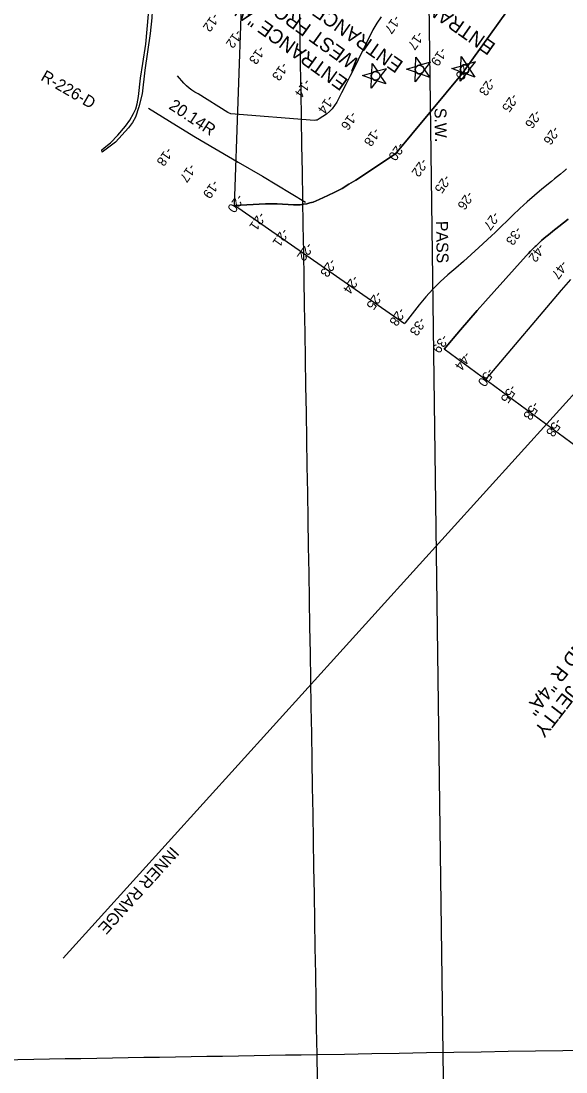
# Model space of a CAD drawing. Extents: x 3879599 to 3900814, y 146526 to 168888.
# Drawn here: x 3887801 to 3889730, y 150452 to 154174 of the extents above; entities that cross this region are included whole.
import ezdxf

# ---------------------------------------------------------------- set-up
doc = ezdxf.new("R2010")
doc.units = 0
for name, color, linetype in [('V-CHAN-NAID', 7, 'Continuous'), ('V-GRID-MAJR', 7, 'Continuous'), ('V-LEVE-TOET', 7, 'Continuous'), ('V-RIVR-JETY', 7, 'Continuous'), ('V-RIVR-RANG', 7, 'Continuous'), ('V-RIVR-RANG-IDEN', 7, 'Continuous'), ('V-STRM-FMON', 7, 'Continuous'), ('V-TOPO-DPTH', 7, 'Continuous'), ('V-TOPO-MAJR', 7, 'Continuous'), ('V-TOPO-MINR', 7, 'Continuous')]:
    doc.layers.add(name, color=color, linetype=linetype)

msp = doc.modelspace()

# ---------------------------------------------------------------- linework, layer by layer
at = {"layer": 'V-CHAN-NAID'}
for points in [[(3889197.6, 154008.2), (3889199, 154046.4), (3889217.6, 154018.6), (3889213, 154017.3), (3889212.4, 154017.3), (3889211.3, 154017.4), (3889210.3, 154017.3), (3889209.3, 154017.2), (3889208.4, 154017), (3889207.5, 154016.8), (3889206.7, 154016.6), (3889205.7, 154016.2), (3889204.9, 154015.8), (3889204, 154015.4), (3889203.3, 154015), (3889202.6, 154014.5), (3889201.7, 154013.8), (3889201.1, 154013.3), (3889200.4, 154012.5), (3889199.9, 154012), (3889199.3, 154011.2), (3889198.8, 154010.5), (3889198.4, 154009.8), (3889197.9, 154009)], [(3889357.3, 154009.9), (3889358.7, 154048.1), (3889377.3, 154020.3), (3889372.7, 154019), (3889372.1, 154019.1), (3889371, 154019.1), (3889370.1, 154019), (3889369, 154018.9), (3889368.1, 154018.7), (3889367.2, 154018.5), (3889366.4, 154018.3), (3889365.4, 154017.9), (3889364.6, 154017.5), (3889363.7, 154017.1), (3889363, 154016.7), (3889362.3, 154016.2), (3889361.4, 154015.5), (3889360.8, 154015), (3889360.1, 154014.2), (3889359.6, 154013.7), (3889359, 154012.9), (3889358.5, 154012.2), (3889358.1, 154011.5), (3889357.6, 154010.7)], [(3889042.1, 153985.6), (3889043.6, 154023.8), (3889062.2, 153996), (3889057.6, 153994.7), (3889057, 153994.8), (3889055.8, 153994.8), (3889054.9, 153994.7), (3889053.9, 153994.6), (3889053, 153994.4), (3889052.1, 153994.2), (3889051.2, 153994), (3889050.3, 153993.6), (3889049.4, 153993.2), (3889048.6, 153992.8), (3889047.9, 153992.4), (3889047.2, 153991.9), (3889046.3, 153991.2), (3889045.7, 153990.7), (3889045, 153989.9), (3889044.5, 153989.4), (3889043.9, 153988.6), (3889043.4, 153987.9), (3889042.9, 153987.2), (3889042.5, 153986.4)], [(3889070.7, 153975.1), (3889094.4, 154005.2), (3889057.6, 153994.7), (3889058.7, 153994.6), (3889059.6, 153994.4), (3889060.6, 153994.1), (3889061.6, 153993.8), (3889062.3, 153993.5), (3889063, 153993.1), (3889063.7, 153992.8), (3889064.3, 153992.4), (3889065.1, 153991.9), (3889065.7, 153991.4), (3889066.5, 153990.7), (3889067.1, 153990.2), (3889067.8, 153989.3), (3889068.4, 153988.6), (3889069, 153987.7), (3889069.5, 153987), (3889069.9, 153986.2), (3889070.2, 153985.4), (3889070.6, 153984.5), (3889070.8, 153983.6), (3889071, 153982.8), (3889071.2, 153982.1), (3889071.3, 153981.1), (3889071.4, 153980.4), (3889071.4, 153979.3), (3889071.4, 153978.6), (3889071.3, 153977.6), (3889071.1, 153976.6), (3889071, 153975.8)], [(3889197.1, 153997.1), (3889197, 153992.3), (3889165.6, 154003.8), (3889197.7, 154013), (3889197.6, 154008.2), (3889197.2, 154007.4), (3889197, 154006.6), (3889196.7, 154005.4), (3889196.5, 154004.5), (3889196.3, 154003.4), (3889196.3, 154002.3), (3889196.3, 154001.3), (3889196.4, 154000.5), (3889196.5, 153999.5), (3889196.7, 153998.6), (3889196.9, 153997.7)], [(3889219.3, 153988.9), (3889195.7, 153958.9), (3889197.1, 153997.1), (3889197.4, 153996.3), (3889197.9, 153995.3), (3889198.3, 153994.6), (3889198.8, 153993.7), (3889199.4, 153992.9), (3889199.9, 153992.2), (3889200.6, 153991.5), (3889201.1, 153990.9), (3889202, 153990.2), (3889202.8, 153989.6), (3889203.7, 153989), (3889204.5, 153988.6), (3889205.5, 153988.1), (3889206.6, 153987.7), (3889207.6, 153987.4), (3889208.4, 153987.2), (3889209.4, 153987), (3889210.4, 153986.9), (3889211.5, 153986.8), (3889212.5, 153986.9), (3889213.4, 153986.9), (3889214.5, 153987.1), (3889215.6, 153987.4), (3889216.6, 153987.7), (3889217.6, 153988.1), (3889218.4, 153988.4)], [(3889226.2, 153997.7), (3889249.8, 154027.7), (3889213, 154017.3), (3889214.1, 154017.2), (3889215, 154017), (3889216, 154016.7), (3889217.1, 154016.3), (3889217.7, 154016.1), (3889218.4, 154015.7), (3889219.1, 154015.4), (3889219.8, 154015), (3889220.5, 154014.5), (3889221.1, 154014), (3889221.9, 154013.3), (3889222.5, 154012.8), (3889223.2, 154011.9), (3889223.9, 154011.2), (3889224.4, 154010.3), (3889224.9, 154009.6), (3889225.3, 154008.8), (3889225.6, 154008), (3889226, 154007), (3889226.3, 154006.2), (3889226.5, 154005.4), (3889226.6, 154004.7), (3889226.7, 154003.7), (3889226.8, 154003), (3889226.8, 154001.9), (3889226.8, 154001.2), (3889226.7, 154000.2), (3889226.6, 153999.2), (3889226.4, 153998.4)], [(3889226.2, 153997.7), (3889229.1, 154001.4), (3889247.8, 153973.6), (3889216.4, 153985.2), (3889219.3, 153988.9), (3889220, 153989.4), (3889220.9, 153990), (3889221.7, 153990.7), (3889222.5, 153991.4), (3889222.9, 153991.8), (3889223.4, 153992.4), (3889223.9, 153993.1), (3889224.3, 153993.7), (3889224.8, 153994.5), (3889225.1, 153995.1), (3889225.5, 153995.9), (3889225.8, 153996.6), (3889226, 153997.2)], [(3889356.8, 153998.8), (3889356.7, 153994), (3889325.3, 154005.5), (3889357.4, 154014.7), (3889357.3, 154009.9), (3889356.9, 154009.1), (3889356.7, 154008.3), (3889356.4, 154007.1), (3889356.2, 154006.2), (3889356.1, 154005.1), (3889356, 154004), (3889356, 154003.1), (3889356.1, 154002.2), (3889356.2, 154001.2), (3889356.4, 154000.3), (3889356.6, 153999.4)], [(3889379, 153990.7), (3889355.4, 153960.6), (3889356.8, 153998.8), (3889357.1, 153998), (3889357.6, 153997), (3889358, 153996.3), (3889358.5, 153995.4), (3889359.1, 153994.6), (3889359.6, 153994), (3889360.3, 153993.2), (3889360.8, 153992.6), (3889361.7, 153991.9), (3889362.5, 153991.3), (3889363.4, 153990.7), (3889364.2, 153990.3), (3889365.3, 153989.8), (3889366.3, 153989.4), (3889367.3, 153989.1), (3889368.1, 153988.9), (3889369.1, 153988.7), (3889370.1, 153988.6), (3889371.2, 153988.5), (3889372.2, 153988.6), (3889373.1, 153988.7), (3889374.2, 153988.8), (3889375.3, 153989.1), (3889376.3, 153989.4), (3889377.3, 153989.8), (3889378.1, 153990.1)], [(3889385.9, 153999.4), (3889409.5, 154029.4), (3889372.7, 154019), (3889373.8, 154018.9), (3889374.7, 154018.7), (3889375.7, 154018.4), (3889376.8, 154018.1), (3889377.4, 154017.8), (3889378.1, 154017.4), (3889378.8, 154017.1), (3889379.5, 154016.7), (3889380.2, 154016.2), (3889380.8, 154015.7), (3889381.6, 154015), (3889382.2, 154014.5), (3889383, 154013.6), (3889383.6, 154012.9), (3889384.1, 154012), (3889384.6, 154011.3), (3889385, 154010.5), (3889385.4, 154009.7), (3889385.7, 154008.8), (3889386, 154007.9), (3889386.2, 154007.1), (3889386.3, 154006.4), (3889386.5, 154005.4), (3889386.5, 154004.7), (3889386.5, 154003.6), (3889386.5, 154002.9), (3889386.4, 154001.9), (3889386.3, 154000.9), (3889386.1, 154000.1)], [(3889385.9, 153999.4), (3889388.8, 154003.1), (3889407.5, 153975.4), (3889376.1, 153986.9), (3889379, 153990.7), (3889379.7, 153991.1), (3889380.6, 153991.7), (3889381.4, 153992.4), (3889382.2, 153993.1), (3889382.6, 153993.5), (3889383.1, 153994.1), (3889383.6, 153994.8), (3889384, 153995.4), (3889384.5, 153996.2), (3889384.8, 153996.8), (3889385.2, 153997.6), (3889385.5, 153998.4), (3889385.7, 153998.9)], [(3889041.7, 153974.5), (3889041.5, 153969.7), (3889010.1, 153981.3), (3889042.3, 153990.4), (3889042.1, 153985.6), (3889041.8, 153984.8), (3889041.5, 153984), (3889041.2, 153982.8), (3889041, 153981.9), (3889040.9, 153980.8), (3889040.9, 153979.7), (3889040.9, 153978.8), (3889040.9, 153977.9), (3889041.1, 153976.9), (3889041.3, 153976), (3889041.5, 153975.1)], [(3889063.9, 153966.4), (3889040.3, 153936.3), (3889041.7, 153974.5), (3889042, 153973.7), (3889042.4, 153972.7), (3889042.9, 153972), (3889043.4, 153971.1), (3889043.9, 153970.3), (3889044.5, 153969.7), (3889045.1, 153968.9), (3889045.7, 153968.3), (3889046.5, 153967.6), (3889047.4, 153967), (3889048.3, 153966.4), (3889049.1, 153966), (3889050.1, 153965.5), (3889051.2, 153965.1), (3889052.2, 153964.8), (3889052.9, 153964.6), (3889054, 153964.4), (3889055, 153964.3), (3889056.1, 153964.2), (3889057.1, 153964.3), (3889058, 153964.4), (3889059.1, 153964.5), (3889060.2, 153964.8), (3889061.2, 153965.1), (3889062.2, 153965.5), (3889062.9, 153965.8)], [(3889070.7, 153975.1), (3889073.7, 153978.8), (3889092.3, 153951.1), (3889060.9, 153962.6), (3889063.9, 153966.4), (3889064.6, 153966.8), (3889065.5, 153967.4), (3889066.3, 153968.1), (3889067, 153968.8), (3889067.4, 153969.3), (3889067.9, 153969.8), (3889068.5, 153970.5), (3889068.9, 153971.1), (3889069.4, 153971.9), (3889069.7, 153972.5), (3889070.1, 153973.3), (3889070.4, 153974.1), (3889070.6, 153974.6)]]:
    msp.add_lwpolyline(points, close=True, dxfattribs=at)
for centre in [(3889211.6, 154002.1), (3889371.3, 154003.8), (3889056.1, 153979.5)]:
    msp.add_circle(centre, 15.3, dxfattribs=at)
at = {"layer": 'V-GRID-MAJR'}
for points in [[(3888895.8, 147678.8), (3888848.8, 150514.5), (3888748.3, 156574.8), (3888664.2, 161644.6)], [(3885282.4, 150455.6), (3888848.8, 150514.5), (3891944, 150566)]]:
    msp.add_spline(points, degree=3, dxfattribs=at)
at = {"layer": 'V-LEVE-TOET'}
msp.add_lwpolyline([(3888252.6, 153865.4), (3888350.9, 153803.5), (3888418.1, 153762.8), (3888569.9, 153673.9), (3888655.7, 153624.2), (3888807.5, 153532.6)], dxfattribs=at)
at = {"layer": 'V-RIVR-JETY'}
for points in [[(3888270.1, 154304.1), (3888267.2, 154257.8), (3888264.2, 154185.3), (3888258.3, 154129.9), (3888239.4, 154000.5), (3888229.7, 153915.8), (3888218.4, 153870.1), (3888206, 153834.1), (3888195.1, 153814.4), (3888181.7, 153796.2), (3888135.4, 153745.5), (3888087.8, 153710), (3888086.3, 153717.3)], [(3888086.3, 153717.3), (3888101.4, 153729.4), (3888118, 153742.1), (3888143.8, 153769.2), (3888171.2, 153801.2), (3888185.9, 153823), (3888199.2, 153846.5), (3888206.7, 153862.6), (3888212.3, 153881.1), (3888216.5, 153906.6), (3888224.1, 153972.1), (3888232.5, 154023.4), (3888242.8, 154092.1), (3888252.3, 154198.1)]]:
    msp.add_lwpolyline(points, dxfattribs=at)
at = {"layer": 'V-RIVR-RANG'}
for points in [[(3887950.4, 150855.4), (3895383.9, 159071.9)], [(3889221.4, 156009), (3889317.4, 148746.9)]]:
    msp.add_lwpolyline(points, dxfattribs=at)
at = {"layer": 'V-TOPO-DPTH'}
for p, q in [((3888556.8, 153520.2), (3888603.3, 154846.2)), ((3889157.8, 153101.4), (3888556.8, 153520.2)), ((3889882.4, 152581.8), (3889298.2, 153011.4))]:
    msp.add_line(p, q, dxfattribs=at)
for points in [[(3889589.5, 154304.9), (3889363.9, 153989.9), (3889126.6, 153704.1), (3888985.5, 153610.9), (3888961.5, 153595.8), (3888937.1, 153581.4), (3888912.2, 153568.2), (3888886.8, 153555.6), (3888856.8, 153541.6), (3888846, 153537), (3888834.9, 153532.9), (3888823.6, 153529.6), (3888812.1, 153526.8), (3888800.5, 153524.9), (3888788.8, 153523.5), (3888777, 153523.1), (3888765.2, 153523.2), (3888707.1, 153526.2), (3888701.9, 153526.5), (3888696.8, 153526.7), (3888691.7, 153526.8), (3888686.6, 153526.9), (3888681.4, 153526.9), (3888676.3, 153526.8), (3888671.2, 153526.7), (3888666, 153526.4), (3888556.8, 153520.2)], [(3888556.8, 153520.2), (3888666, 153526.4), (3888671.2, 153526.7), (3888676.3, 153526.8), (3888681.4, 153526.9), (3888686.6, 153526.9), (3888691.7, 153526.8), (3888696.8, 153526.7), (3888701.9, 153526.5), (3888707.1, 153526.2), (3888765.2, 153523.2), (3888777, 153523.1), (3888788.8, 153523.5), (3888800.5, 153524.9), (3888812.1, 153526.8), (3888823.6, 153529.6), (3888834.9, 153532.9), (3888846, 153537), (3888856.8, 153541.6), (3888886.8, 153555.6), (3888912.2, 153568.2), (3888937.1, 153581.4), (3888961.5, 153595.8), (3888985.5, 153610.9), (3889126.6, 153704.1), (3889363.9, 153989.9), (3889589.5, 154304.9)], [(3889732, 153650.6), (3889723, 153642.6), (3889720.7, 153640.7), (3889710.4, 153632), (3889700.1, 153623.3), (3889689.6, 153614.7), (3889679.1, 153606.2), (3889644.6, 153578.3), (3889618.1, 153556.3), (3889592, 153533.7), (3889566.7, 153510.3), (3889541.8, 153486.4), (3889518.6, 153463.4), (3889505.6, 153450.7), (3889492.5, 153438), (3889479.3, 153425.5), (3889466, 153413.1), (3889421.7, 153372), (3889394.6, 153347.3), (3889367.3, 153322.8), (3889339.7, 153298.6), (3889311.9, 153274.7), (3889284.8, 153250.2), (3889258.7, 153224.6), (3889234.1, 153197.6), (3889210.7, 153169.5), (3889160.2, 153105.2), (3889159.4, 153103.9), (3889157.8, 153101.4)], [(3889732, 153650.6), (3889723, 153642.6), (3889720.7, 153640.7), (3889710.4, 153632), (3889700.1, 153623.3), (3889689.6, 153614.7), (3889679.1, 153606.2), (3889644.6, 153578.3), (3889618.1, 153556.3), (3889592, 153533.7), (3889566.7, 153510.3), (3889541.8, 153486.4), (3889518.6, 153463.4), (3889505.6, 153450.7), (3889492.5, 153438), (3889479.3, 153425.5), (3889466, 153413.1), (3889421.7, 153372), (3889394.6, 153347.3), (3889367.3, 153322.8), (3889339.7, 153298.6), (3889311.9, 153274.7), (3889284.8, 153250.2), (3889258.7, 153224.6), (3889234.1, 153197.6), (3889210.7, 153169.5), (3889160.2, 153105.2), (3889159.4, 153103.9), (3889157.8, 153101.4)], [(3889298.2, 153011.4), (3889356.6, 153080.2), (3889386, 153114.4), (3889415.5, 153148.5), (3889445.4, 153182.3), (3889475.4, 153216), (3889589.2, 153342.1), (3889596.9, 153350.6), (3889604.8, 153359), (3889612.8, 153367.2), (3889620.9, 153375.4), (3889624, 153378.4), (3889633.5, 153387.6), (3889643.1, 153396.5), (3889653.1, 153405.1), (3889663.3, 153413.5), (3889673.7, 153421.7), (3889684, 153429.9), (3889694.3, 153438), (3889704.7, 153446.2), (3889737.4, 153472.1)], [(3889298.2, 153011.4), (3889356.6, 153080.2), (3889386, 153114.4), (3889415.5, 153148.5), (3889445.4, 153182.3), (3889475.4, 153216), (3889589.2, 153342.1), (3889596.9, 153350.6), (3889604.8, 153359), (3889612.8, 153367.2), (3889620.9, 153375.4), (3889624, 153378.4), (3889633.5, 153387.6), (3889643.1, 153396.5), (3889653.1, 153405.1), (3889663.3, 153413.5), (3889673.7, 153421.7), (3889684, 153429.9), (3889694.3, 153438), (3889704.7, 153446.2), (3889737.4, 153472.1)]]:
    msp.add_lwpolyline(points, dxfattribs=at)
at = {"layer": 'V-TOPO-MAJR'}
msp.add_lwpolyline([(3889745.4, 153258.6), (3889729.4, 153239.7), (3889713.5, 153220.9), (3889459.3, 152921), (3889456.9, 152918.1), (3889454.5, 152915.2), (3889452.1, 152912.3), (3889449.7, 152909.4), (3889445, 152903.5)], dxfattribs=at)
at = {"layer": 'V-TOPO-MINR'}
for points in [[(3889589.5, 154304.9), (3889363.9, 153989.9), (3889126.6, 153704.1), (3888985.5, 153610.9), (3888961.5, 153595.8), (3888937.1, 153581.4), (3888912.2, 153568.2), (3888886.8, 153555.6), (3888856.8, 153541.6), (3888846, 153537), (3888834.9, 153532.9), (3888823.6, 153529.6), (3888812.1, 153526.8), (3888800.5, 153524.9), (3888788.8, 153523.5), (3888777, 153523.1), (3888765.2, 153523.2), (3888707.1, 153526.2), (3888701.9, 153526.5), (3888696.8, 153526.7), (3888691.7, 153526.8), (3888686.6, 153526.9), (3888681.4, 153526.9), (3888676.3, 153526.8), (3888671.2, 153526.7), (3888666, 153526.4), (3888556.8, 153520.2)], [(3889075.8, 154189.3), (3889060.1, 154166.6), (3889046.2, 154142.4), (3888994.3, 154037), (3888979.8, 154007.6), (3888965.1, 153978.1), (3888950.3, 153948.8), (3888935.4, 153919.5), (3888918.5, 153886.6), (3888911.1, 153874.6), (3888902.7, 153863.4), (3888892.7, 153853.6), (3888881.8, 153844.7), (3888856.8, 153827.3), (3888852.9, 153825.1), (3888848.9, 153823.4), (3888844.6, 153822.4), (3888840.2, 153821.9), (3888543.3, 153845), (3888533, 153850.4), (3888427.8, 153916.4), (3888416.5, 153922.2), (3888405.7, 153928.7), (3888395.6, 153936), (3888386.3, 153944.3), (3888377.5, 153953.4), (3888355, 153979.6)], [(3889732, 153650.6), (3889723, 153642.6), (3889720.7, 153640.7), (3889710.4, 153632), (3889700.1, 153623.3), (3889689.6, 153614.7), (3889679.1, 153606.2), (3889644.6, 153578.3), (3889618.1, 153556.3), (3889592, 153533.7), (3889566.7, 153510.3), (3889541.8, 153486.4), (3889518.6, 153463.4), (3889505.6, 153450.7), (3889492.5, 153438), (3889479.3, 153425.5), (3889466, 153413.1), (3889421.7, 153372), (3889394.6, 153347.3), (3889367.3, 153322.8), (3889339.7, 153298.6), (3889311.9, 153274.7), (3889284.8, 153250.2), (3889258.7, 153224.6), (3889234.1, 153197.6), (3889210.7, 153169.5), (3889160.2, 153105.2), (3889159.4, 153103.9), (3889157.8, 153101.4)], [(3889737.4, 153472.1), (3889704.7, 153446.2), (3889694.3, 153438), (3889684, 153429.9), (3889673.7, 153421.7), (3889663.3, 153413.5), (3889653.1, 153405.1), (3889643.1, 153396.5), (3889633.5, 153387.6), (3889624, 153378.4), (3889620.9, 153375.4), (3889612.8, 153367.2), (3889604.8, 153359), (3889596.9, 153350.6), (3889589.2, 153342.1), (3889475.4, 153216), (3889445.4, 153182.3), (3889415.5, 153148.5), (3889386, 153114.4), (3889356.6, 153080.2), (3889298.2, 153011.4)]]:
    msp.add_lwpolyline(points, dxfattribs=at)

# ---------------------------------------------------------------- texts
at = {"layer": 'V-CHAN-NAID'}
for s, rotation, p in [('ENTRANCE "A" RANGE EAST FRONT PASSING (-20.1)', 145.0553, (3889484.3, 154091)), ('ENTRANCE "A" RANGE FRONT (-20.1)', 144.9757, (3889157.6, 154027.6)), ('WEST FRONT (-20.1)', 144.314, (3889003.7, 154033.4)), ('ENTRANCE "A" RANGE', 144.314, (3888961.8, 153964.5)), ('END R "4A"', 232.244, (3889800.5, 152022)), ('EAST JETTY', 232.244, (3889857.7, 151978))]:
    msp.add_text(s, height=50, rotation=rotation, dxfattribs=at).set_placement(p)
at = {"layer": 'V-RIVR-RANG'}
for s, rotation, p in [('-12', 234.5083, (3888480, 154204.1)), ('-17', 235.1083, (3889122.2, 154197)), ('-12', 234.5083, (3888561.5, 154146.2)), ('-17', 235.1083, (3889204.4, 154140)), ('-13', 234.5083, (3888643.3, 154088.6)), ('-19', 235.1083, (3889286.4, 154082.9)), ('-13', 234.5083, (3888724.8, 154030.7)), ('-20', 235.1083, (3889373.7, 154033.2)), ('-14', 234.5083, (3888805.4, 153971.5)), ('-23', 235.1083, (3889456.6, 153977.2)), ('-14', 234.5083, (3888887, 153913.6)), ('-25', 235.1083, (3889538.3, 153919.6)), ('-16', 234.5083, (3888968.6, 153855.9)), ('-26', 235.1083, (3889620, 153861.9)), ('-18', 234.5083, (3889050.3, 153798.2)), ('-26', 235.2513, (3889684.9, 153803.7)), ('-20', 234.5083, (3889136.9, 153747.4)), ('-18', 234.8583, (3888316.1, 153728.6)), ('-17', 234.8583, (3888397.8, 153671)), ('-22', 234.5083, (3889219, 153690.3)), ('-19', 234.8583, (3888479.7, 153613.5)), ('-25', 234.5083, (3889300.2, 153632)), ('-20', 234.8583, (3888566.7, 153563.5)), ('-26', 234.5083, (3889381.3, 153573.5)), ('-21', 234.8583, (3888644.4, 153500.1)), ('-27', 234.6544, (3889472.7, 153501.5)), ('-33', 234.6544, (3889552.7, 153448.2)), ('-21', 234.8583, (3888726.3, 153442.7)), ('-22', 234.8583, (3888813, 153392.2)), ('-42', 234.6544, (3889633.1, 153388.6)), ('-23', 234.8583, (3888895.1, 153335)), ('-47', 234.6544, (3889713.8, 153328.4)), ('-24', 234.8583, (3888976, 153276.3)), ('-25', 234.8583, (3889058.5, 153219.7)), ('-28', 234.8583, (3889140.1, 153161.9)), ('-33', 235.0027, (3889211.8, 153127.4)), ('-39', 235.0027, (3889291.8, 153066.4)), ('-44', 235.0027, (3889371.5, 153005.5)), ('-50', 235.0027, (3889452.9, 152947.6)), ('-55', 235.0027, (3889533.7, 152888.7)), ('-58', 235.0027, (3889614, 152829)), ('-58', 235.0027, (3889694.5, 152769.7))]:
    msp.add_text(s, height=33.5, rotation=rotation, dxfattribs=at).set_placement(p)
at = {"layer": 'V-RIVR-RANG-IDEN'}
msp.add_text('R-226-D', height=41.5, rotation=330.0008, dxfattribs=at).set_placement((3887867.7, 153966.4))
at = {"layer": 'V-STRM-FMON'}
for s, rotation, p in [('20.14R', 326.549, (3888321, 153865.4)), ('S.W.', 270.9171, (3889264.5, 153866.1)), ('PASS', 270.9171, (3889270, 153465.9)), ('INNER RANGE', 227.8026, (3888333, 151253.6))]:
    msp.add_text(s, height=42, rotation=rotation, dxfattribs=at).set_placement(p)

doc.saveas('drawing.dxf')
